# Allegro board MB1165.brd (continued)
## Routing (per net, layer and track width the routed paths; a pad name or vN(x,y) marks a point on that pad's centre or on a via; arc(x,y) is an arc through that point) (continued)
LCD_R4: length 172.7
  TOP w0.102: U4.N8 v5(74.81,136.89)
  TOP w0.127: v1(69.34,49.15) 69.34,51.31 70.99,52.96 81.41,52.96 87.31,47.05 CN18.11 ; v1(44.7,136.02) 43.43,136.02 42.55,136.91 CN5.31
  L3_SIG w0.102: v5(74.81,136.89) 74.19,136.27 73.66,136.27 73.18,135.79 71.27,135.79 70.65,135.17 68.16,135.17 66.85,133.86 56.31,133.86 54.03,136.14 44.83,136.14 v1(44.7,136.02)
  BOTTOM w0.127: v1(69.34,49.15) 64.52,49.15 61.59,52.07 61.59,61.94 53.16,70.37 53.16,80.67 44.55,89.28 44.55,106.45 39.52,111.48 39.52,123.77 36.96,126.34 36.96,131.44 38.61,133.1 43.29,133.1 43.54,133.35 44.7,133.35 45.34,133.99 45.34,135.38 v1(44.7,136.02)
LCD_R5: length 160.1
  TOP w0.127: U4.M9 v5(74.81,136.09) ; CN18.13 86.04,46.8 80.9,51.94 71.25,51.94 70.48,51.18 v1(70.48,50.55) ; CN5.34 v1(49.02,135.64)
  L3_SIG w0.102: v1(49.02,135.64) 53.9,135.64 56.06,133.48 67.03,133.48 68.31,134.76 70.82,134.76 71.32,135.25 73.41,135.25 74.04,135.89 74.55,135.89 74.75,136.09 v5(74.81,136.09)
  BOTTOM w0.127: v1(49.02,135.64) 45.34,131.95 43.94,131.95 43.56,131.57 39.88,131.57 39.62,131.32 38.86,131.32 38.48,130.94 38.48,127 41.05,124.43 41.05,112.33 46.3,107.07 46.3,90.42 54.58,82.14 54.58,71.34 63.65,62.27 63.65,53.06 66.04,50.67 70.36,50.67 v1(70.48,50.55)
LCD_R6: length 158.6
  TOP w0.127: CN5.42 45.21,130.56 45.09,130.43 v1(44.96,130.43) ; v5(74.41,130.36) 74.41,130.8 74.8,131.19 74.8,132.08 U4.M14 ; CN18.15 84.77,46.8 80.01,51.56 72.14,51.56 71.37,50.8 v1(71.37,50.55)
  L3_SIG w0.102: v1(44.96,130.43) 45.16,130.23 48.41,130.23 49.17,129.46 62.83,129.46 65.55,126.75 71.37,126.75 74.41,129.78 v5(74.41,130.36)
  BOTTOM w0.127: v1(71.37,50.55) 71.37,50.8 70.99,51.18 66.17,51.18 64.16,53.19 64.16,62.58 55.19,71.54 55.19,82.35 46.86,90.68 46.86,107.21 41.43,112.65 41.43,124.69 38.86,127.25 38.86,130.81 39.12,131.06 39.75,131.06 39.88,131.19 43.18,131.19 43.94,130.43 v1(44.96,130.43)
LCD_R7: length 148.7
  TOP w0.127: U4.J15 77.61,129.54 v3(75.94,127.87) ; v1(72.9,50.7) 73.25,51.05 79.63,51.05 83.5,47.18 CN18.17 ; CN5.51 v1(43.33,124.21)
  L3_SIG w0.102: v1(43.33,124.21) 43.94,124.21 44.7,124.97 47.5,124.97 47.88,125.35 49.53,125.35 50.42,124.46 62.48,124.46 64.01,122.94 73.91,122.94 74.68,123.7 74.68,126.61 v3(75.94,127.87)
  BOTTOM w0.127: v1(72.9,50.7) 72.9,51.18 71.95,52.13 67.25,52.13 65.25,54.13 65.25,63.11 56.21,72.15 56.21,83.49 47.75,91.95 47.75,107.95 42.19,113.51 42.19,123.06 v1(43.33,124.21)
LED_STLINK: length 38.9
  TOP w0.127: v1(16.26,16.51) R189.1 R188.1 ; v1(38.48,36.45) 38.22,36.71 U21.30
  BOTTOM w0.127: v1(16.26,16.51) 22.23,16.51 26.49,20.78 26.49,24 30.43,27.94 32.64,27.94 34.67,29.97 34.67,33.91 37.21,36.45 v1(38.48,36.45)
LOOP: length 5.6
  TOP w0.127: U22.14 61.81,31.41 64.01,29.21 TP15.1
MFX_SWCLK: length 7.6
  TOP w0.127: U22.37 51.26,36.41 50.16,35.31 46.61,35.31 CN21.3
MFX_SWDIO: length 11.6
  TOP w0.127: U22.34 54.51,39.6 53.72,40.39 46.61,40.39 CN21.1
MIC_CLK: length 137.6
  TOP w0.127: v1(119.13,16.38) 117.98,15.24 117.98,13.97 120.03,11.92 CN25.3
  BOTTOM w0.127: CN28.3 9.29,11.3 25.65,11.3 33.66,3.3 46.1,3.3 51.56,8.76 58.8,8.76 68.9,18.86 72.58,18.86 80.39,26.67 85.85,26.67 88.39,24.13 96.27,24.13 97.54,25.4 JP18.2 100.33,25.4 107.19,18.54 116.97,18.54 v1(119.13,16.38) SB25.1
MIC_DATA: length 154.5
  BOTTOM w0.127: CN25.1 128.38,11.92 130.68,14.22 130.68,15.88 130.05,16.51 SB26.2 128.78,17.14 121.54,17.14 118.62,20.07 107.57,20.07 100.97,26.67 97.03,26.67 95.76,25.4 JP17.2 89.66,25.4 85.98,29.08 81.41,29.08 72.52,20.19 67.56,20.19 56.77,9.4 51.31,9.4 45.59,3.68 34.29,3.68 26.16,11.81 11.18,11.81 9.78,13.21 5.32,13.21 CN28.1
MIC_VDD: length 156.3
  TOP w0.127: U25.1 125.65,15.66 126.36,16.38 C93.1 127.64,18.43 CN25.4 126.03,17.59 123,17.59 R186.2 120.4,14.99 R185.2 119.13,14.86 v1(118.87,15.11) ; v1(9.78,9.4) 9.4,9.02 8,9.02 7.49,9.53 6.48,9.53 5.63,8.68 U26.1
  L3_SIG w0.102: v1(9.78,9.4) 5.97,9.4 3.81,7.24 CN28.4
  BOTTOM w0.127: v1(9.78,9.4) 9.91,9.53 14.1,9.53 15.29,10.72 25.48,10.72 33.43,2.77 46.89,2.77 51.97,7.85 60.68,7.85 70.48,17.65 73.28,17.65 81.03,25.4 JP16.2 84.84,25.4 89.41,20.83 102.36,20.83 106.17,17.02 116.08,17.02 117.98,15.11 v1(118.87,15.11)
MII_TXD0: length 85.7
  TOP w0.127: v1(122.35,123.37) 122.53,123.54 U6.3 ; R36.2 91.69,142.24 92.75,141.19 101.56,141.19 v1(102.11,141.73)
  L3_SIG w0.102: v1(97.92,155.57) 98.81,156.46 102.36,156.46 103,157.1 107.7,157.1 v1(108.46,157.86)
  BOTTOM w0.127: v1(102.11,141.73) 102.11,146.05 98.17,149.99 98.17,155.32 v1(97.92,155.57) 97.33,156.16 SB27.1 ; v1(122.35,123.37) 122.35,127.25 121.51,128.09 121.51,137.44 116.31,142.65 111.56,142.65 111,143.21 111,155.32 v1(108.46,157.86)
NETB2_2: length 17.1
  TOP w0.127: B2.2 58.49,9.59 58.49,10.99 R205.1 R206.1 61.21,12.32 68.58,12.32 68.96,11.94 C103.2 68.96,9.53 B2.3
NETB3_2: length 17.7
  TOP w0.127: R204.1 R203.1 C100.2 89.73,13.15 B3.2 B3.3
NETB4_1: length 47.8
  TOP w0.127: U22.20 59.19,34.41 v1(58.88,34.09) ; B4.1 73.66,8.11 73.66,10.54 76.33,13.21 v1(77.98,13.21) 78.61,13.84 R199.2 C97.2
  L3_SIG w0.102: v1(77.98,13.21) 76.71,14.48 69.6,14.48 60.58,23.5 60.58,33.15 59.64,34.09 v1(58.88,34.09)
NETB4_2: length 43
  TOP w0.127: U22.18 v1(59.51,33.41) ; R198.2 C96.2 v1(74.42,13.08) 74.42,12.7 73.03,11.3 73.03,7.24 74.94,5.32 B4.2
  L3_SIG w0.102: v1(59.51,33.41) 59.69,33.41 60.33,32.77 60.33,23.11 69.47,13.97 73.53,13.97 v1(74.42,13.08)
NETB4_3: length 45.3
  TOP w0.127: v1(58.88,33.4) 59.38,33.9 U22.19 ; C95.2 R197.2 v1(73.03,13.08) 72.52,12.57 72.52,6.6 74.8,4.32 77.45,4.32 B4.3
  L3_SIG w0.102: v1(58.88,33.4) 59.97,32.31 59.97,22.83 69.72,13.08 v1(73.03,13.08)
NETB4_4: length 55.4
  TOP w0.127: U22.39 52.68,35.41 53.09,35.81 53.7,35.81 v1(53.82,35.69) ; B4.4 84.84,11.31 v1(84.84,13.08) 84.84,13.34 R201.2 C99.2
  L3_SIG w0.102: v1(84.84,13.08) 82.3,15.62 69.6,15.62 61.34,23.88 61.34,33.53 60.1,34.77 54.74,34.77 v1(53.82,35.69)
NETB4_6: length 49.3
  TOP w0.127: v1(53.09,35.18) 52.96,35.18 52.68,34.9 U22.40 ; C98.2 R200.2 81.79,13.59 v1(81.79,13.07) B4.6
  L3_SIG w0.102: v1(81.79,13.07) 79.87,14.99 69.66,14.99 68.73,15.91 64.93,19.71 60.96,23.68 60.96,33.4 59.82,34.54 53.72,34.54 v1(53.09,35.18)
NETBT1_1: length 23.8
  TOP w0.254: BT1.1 47.88,78.23 40.77,85.34 JP10.3
NETC2_1: length 6.9
  TOP w0.508: C4.1 137.79,167.26 C2.1 R1.2 134.85,168.68 U1.6
NETC5_1: length 10
  TOP w0.508: R16.2 138.3,158.2 ; R16.2 137.69,157.61 ; R16.2 138.91,157.61 ; U2.1 135.85,159.11 ; U2.1 135.14,160.21 ; U2.1 135.14,158 ; U2.1 134.43,159.11 ; 137.69,159.13 R7.1 ; R7.1 138.3,158.53 ; R7.1 138.91,159.13 ; C5.1 135.84,161.93 ; C5.1 135,162.89 ; C5.1 135,160.96
NETC6_2: length 50.9
  TOP w0.127: CN1.31 64.01,166.53 v1(64.01,163.96) 64.01,160.2 64.17,160.04 65.55,160.04 C6.2
  BOTTOM w0.127: v1(64.01,163.96) 57.15,163.96 51.82,158.62 42.29,158.62 38.61,154.94 38.61,145.29 39.5,144.4 SB46.1
NETC7_2: length 81.8
  TOP w0.127: CN1.27 71.63,166.21 71.63,162.31 72.14,161.8 C7.2
  TOP w0.155: v1(69.44,157.84) 69.6,157.99 69.6,159.89 69.98,160.27 C7.2
  BOTTOM w0.127: 116.2,133.1 SB66.1 115.32,133.99 108.2,133.99 106.3,135.89 106.3,153.06 102.86,156.5 102.86,157.75 101.55,159.05 93.65,159.05 93.24,158.65 80.82,158.65 80.34,158.17 70,158.17 69.67,157.84 v1(69.44,157.84)
NETC8_2: length 27
  TOP w0.127: CN1.33 61.09,166.15 v1(61.09,162.62) C8.2
  BOTTOM w0.127: SB33.1 48.9,152.02 48.9,153.16 58.36,162.62 v1(61.09,162.62)
NETC9_2: length 34.5
  TOP w0.127: C9.2 v1(62.48,161.99) 62.48,165 CN1.34
  BOTTOM w0.127: v1(62.48,161.99) 62.29,161.8 59.56,161.8 50.67,152.91 50.67,151.83 49.94,151.09 49.94,150.01 48.39,148.46 45.47,148.46 44.7,147.7 43.69,147.7 42.71,146.72 41.24,146.72 40.64,147.32
NETC10_2: length 76.9
  TOP w0.127: v1(68.55,156.16) 68.07,156.64 68.07,159.51 C10.2 68.83,166.47 CN1.29
  BOTTOM w0.127: SB68.1 108.58,131.44 108.58,133.15 105.92,135.81 105.92,153.03 101.73,157.23 101.73,157.66 100.91,158.47 95.1,158.47 94.39,157.76 81.25,157.76 80.87,157.38 70.51,157.38 69.8,156.67 69.06,156.67 v1(68.55,156.16)
NETC11_1: length 47.2
  TOP w0.127: v1(74.5,158.65) 74.6,158.75 R8.2 C11.1
  BOTTOM w0.127: SB69.2 50.32,133.25 50.32,138.48 55.02,143.18 55.02,148.91 60.35,154.24 63.39,154.24 67.44,158.29 69.19,158.29 69.32,158.42 74.27,158.42 v1(74.5,158.65)
NETC12_2: length 48.1
  TOP w0.127: C12.2 R9.1 78.51,159.74 v1(78.51,160.27)
  BOTTOM w0.127: v1(78.51,160.27) 77.6,160.27 76.96,159.64 73.43,159.64 73.18,159.38 69.04,159.38 68.78,159.13 66.67,159.13 63.5,155.96 60.33,155.96 53.75,149.38 53.75,143.66 48.51,138.43 48.51,137.41 47.75,136.65
NETC13_2: length 54.7
  TOP w0.127: C13.2 R10.1 81.97,159.59 v1(81.97,160.73)
  BOTTOM w0.127: SB49.2 44.83,141.35 45.59,142.11 49.15,142.11 52.6,145.57 52.6,150.01 59.69,157.1 62.99,157.1 66.07,160.17 67.87,160.17 68.39,160.7 72.97,160.7 73.17,160.5 76.28,160.5 76.97,161.19 81.51,161.19 v1(81.97,160.73)
NETC14_2: length 52
  TOP w0.127: v1(85.9,162.92) 85.85,162.86 85.85,162.31 86.23,161.93 86.23,159.38 R11.1 C14.2
  BOTTOM w0.127: SB41.2 48.39,147.57 50.39,149.58 50.39,150.85 51.44,151.89 51.44,152.78 59.94,161.29 63.63,161.29 65.38,163.04 85.78,163.04 v1(85.9,162.92)
NETC15_1: length 92.3
  TOP w0.127: C15.1 R13.1 R12.2 89.15,159.51 89.15,165.99 88.77,166.37 87.38,166.37 86.49,167.26 86.49,168.5 v1(86.36,168.63)
  BOTTOM w0.127: v1(86.36,168.63) 86.11,168.88 44.68,168.88 42.55,166.75 42.55,160.66 37.21,155.32 37.21,143.89 38.02,143.08 38.02,140.59 38.53,140.08 40.39,140.08 40.64,139.83 SB52.2
NETC16_2: length 10.6
  TOP w0.127: R15.1 R14.1 C16.2 104.27,166.59 CN1.1
NETC17_1: length 1.7
  TOP w0.127: 64.14,159.05 64.32,158.88 C17.1
NETC18_2: length 78.4
  TOP w0.127: SB1.1 70.49,159 70.49,157.36 v1(69.34,156.21) ; C18.2 70.87,158.88
  BOTTOM w0.127: v1(69.34,156.21) 69.77,156.21 70.66,157.1 81.13,157.1 81.51,157.48 94.61,157.48 95.18,158.05 99.2,158.05 100.41,156.84 100.89,156.84 105.21,152.53 105.21,135.61 107.59,133.22 107.59,127.64 107.87,127.36 112.27,127.36 112.67,127.76 115.32,127.76 SB75.1
NETC20_1: length 6.3
  TOP w0.203: X1.2 75.44,152.65 C20.1 R20.2
NETC21_1: length 5.7
  TOP w0.203: X2.1 82.63,153.46 82.63,152.6 82.09,152.06 82.09,151.17 C21.1 R18.1
NETC22_1: length 5.7
  TOP w0.203: X2.2 83.06,153.28 83.06,152.4 82.51,151.85 82.51,151.02 C22.1 R19.1
NETC24_2: length 2.8
  TOP w0.127: R30.1 C24.2 R31.1
NETC25_1: length 2.4
  TOP w0.127: C25.1 26.89,133.77 U5.1
NETC25_2: length 2.1
  TOP w0.127: C25.2 26.02,133.12 U5.2
NETC27_2: length 2.4
  TOP w0.127: C27.2 26.67,132.47 U5.3
NETC30_1: length 13.9
  TOP w0.254: JP7.1 145.29,125.22 X4.1 137.54,125.22 C30.1
NETC32_1: length 12.3
  TOP w0.127: v5(81.21,134.49) U4.E11
  TOP w0.508: C32.1 82.09,125.81 80.53,127.36 80.53,128.21 80.49,128.25 80.49,129.46 80.06,129.9 v1(79.86,129.9)
  BOTTOM w0.127: v5(81.21,134.49) 80.83,134.11 80.16,134.11 80.04,133.99 80.04,132.37 80.01,132.33
  BOTTOM w0.381: v1(79.86,129.9) 79.93,129.97 79.93,130.56 80.01,130.63 80.01,132.33
NETC33_2: length 7.2
  TOP w0.254: X4.2 140.72,121.23 139.14,122.81 R67.2 C33.2
NETC35_1: length 21.4
  TOP w0.508: L1.2 7.21,118.11 ; L1.2 6.6,118.76 ; L1.2 6.6,117.46 ; L1.2 5.99,118.11 ; 1.28,118.21 CN8.8 2.44,117.31 ; C36.1 5.69,118.11 ; C36.1 4.47,118.11 ; C36.1 5.08,117.46 ; 2.44,109.01 CN8.9 1.28,108.1 ; 4.47,107.95 C45.1 ; C45.1 5.08,108.6 ; C45.1 5.69,107.95 ; 3.56,117.46 C35.1 ; C35.1 4.17,118.11 ; C35.1 2.95,118.11 ; C44.1 4.17,107.95 ; C44.1 2.95,107.95 ; C44.1 3.56,108.6 ; CN8.6 5.46,110.88 ; CN8.6 3.46,110.88 ; CN8.6 4.46,110.14 ; CN8.7 5.46,115.43 ; CN8.7 4.46,116.17 ; CN8.7 3.46,115.43 ; 5.01,114.46 CN8.5 3.26,114.46
NETC37_1: length 8.8
  TOP w0.508: SB13.1 11.43,115.82 12.07,116.46 13.84,116.46 SB14.2 15.62,116.46 C37.1 17.09,116.26 U7.1
NETC39_1: length 8
  TOP w0.203: U8.28 28.7,109.86 R81.2 C39.1 27.81,113.54 X5.1
NETC40_1: length 7.6
  TOP w0.203: U8.27 29.2,110.61 R81.1 C40.1 29.34,113.54 X5.2
NETC41_1: length 12.4
  TOP w0.102: U9.B5 81.31,102.77 83.11,102.77 83.79,103.45 83.79,105.87 84,106.07 84,107.95
  TOP w0.127: 84,107.95 84,110.41 C41.1 R79.2
NETC42_1: length 5
  TOP w0.127: U8.29 28.2,109.72 27.81,110.11 v1(27.05,110.11) 26.92,110.11 C42.1
  BOTTOM w0.127: C147.1 26.67,110.11 v1(27.05,110.11)
NETC43_1: length 19.7
  TOP w0.254: U8.15 29.7,102.74 ; v1(30.1,111.53) 30.23,111.53 30.86,110.9 C43.1 29.7,109.58 U8.26
  TOP w0.381: v1(32,102.79) 32,101.47 C48.1 31.11,101.35 29.97,102.49 29.95,102.49 29.7,102.74
  BOTTOM w0.381: v1(32,102.79) 32,103 32.64,103.63 32.64,105.28 32.72,105.36 32.72,109.7 30.89,111.53 v1(30.1,111.53)
NETC53_2: length 1.9
  TOP w0.508: C53.2 24.2,69.78 U17.4
NETC54_2: length 21.8
  TOP w0.508: C54.2 30.17,69.78 U17.3 ; C54.2 30.23,73.12 29.06,74.28 D12.2 D11.2 D10.2 D9.2 D8.2 D7.2 ; C54.2 C56.2 28.32,67.82 U17.1
NETC63_1: length 9
  TOP w0.508: 65.53,51.47 L4.2 66.14,52.12 ; 65.91,48.31 65.91,49.28 ; 65.91,48.31 65.07,48.31 ; 65.91,48.31 65.91,47.35 ; 65.91,48.31 66.75,48.31 ; 65.28,49.73 C63.1 ; C63.1 65.93,50.34 ; C63.1 65.28,50.95 ; CN18.45 65.72,46.75
NETC63_2: length 11.3
  TOP w0.508: 63.18,46.1 CN18.49 62.61,44.5 ; 62.28,48.31 C66.2 ; C66.2 63.96,48.31 ; C66.2 63.12,47.35 ; C66.2 63.12,49.28 ; L3.2 64.11,52.12 ; L3.2 62.89,52.12 ; L3.2 63.5,51.47 ; 63.75,49.73 C63.2 ; C63.2 63.75,50.95 ; C63.2 63.11,50.34 ; CN18.47 64.45,46.27
NETC64_1: length 27.8
  TOP w0.508: 22.1,46.83 D13.3 ; D13.3 22.1,47.85 ; D13.3 22.77,47.34 ; Z1.2 23.24,52.35 ; Z1.2 22.03,51.31 ; Z1.2 24.44,51.31 ; Z1.2 23.24,50.27 ; C64.1 22.1,49.38 ; C64.1 22.1,48.16 ; C64.1 22.75,48.77
  TOP w1.143: 22.15,53.19 21.62,53.72 12.7,53.72 11.68,52.7 9.02,52.7 6.52,50.2 L5.1
NETC64_2: length 27
  TOP w0.508: 19.44,50.27 Z1.1 ; Z1.1 20.64,51.31 ; Z1.1 19.44,52.35 ; Z1.1 18.23,51.31 ; 19.93,48.77 C64.2 ; C64.2 20.57,49.38 ; C64.2 20.57,48.16 ; 20.15,47.34 D13.2 ; D13.2 20.83,47.85 ; D13.2 20.83,46.83 ; 7.91,50.2 L5.2 ; L5.2 10.3,50.2 ; L5.2 9.1,51.4 ; L5.2 9.1,49.01 ; CN19.2 7.54,35.84 ; CN19.2 9.86,34.62 ; CN19.2 5.23,34.62 ; CN19.2 7.54,33.4 ; 4.45,37.31 CN19.3 ; CN19.3 3.23,39.62 ; CN19.3 5.66,39.62 ; CN19.3 4.45,41.94
NETC68_2: length 5.9
  TOP w0.127: C68.2 113.92,33.25 114.53,32.64 116.46,32.64 117.36,31.74 U23.C9
NETC69_1: length 5.6
  TOP w0.127: v1(115.01,33.53) 115.01,34.11 C69.1 ; U23.D7 v2(117.61,30.33)
  L3_SIG w0.102: v2(117.61,30.33) 115.01,32.93 v1(115.01,33.53)
NETC69_2: length 60.7
  TOP w0.127: R212.2 140.37,1.18 CN27.2 136.51,1.18 v1(135.2,2.49) ; v1(114.58,35.18) 114.68,35.28 114.68,35.31 C69.2 ; R160.1 v1(111.63,27.58)
  L3_SIG w0.102: v1(135.2,2.49) 132.51,2.49 130.81,4.19 130.81,6.99 127.64,10.16 119.89,10.16 111.63,18.41 v1(111.63,27.58)
  BOTTOM w0.127: v1(114.58,35.18) 113.41,34.01 113.41,31.95 111.63,30.17 v1(111.63,27.58)
NETC70_1: length 3.8
  TOP w0.127: U23.D9 117.86,32.38 116.71,33.53 C70.1
NETC74_1: length 7.2
  TOP w0.127: U23.E6 v2(118.61,29.83) ; C74.1 v1(122.3,33.53)
  L3_SIG w0.102: v2(118.61,29.83) 119.02,30.25 119.02,30.76 119.38,31.11 120.65,31.11 121.89,32.36 121.89,33.12 v1(122.3,33.53)
NETC75_1: length 6.2
  TOP w0.127: U23.H8 120.85,30.58 122.45,32.18 124.38,32.18 C75.1
NETC75_2: length 5.4
  TOP w0.127: U23.G8 v2(119.61,30.83) ; v1(122.53,32.74) 123.42,32.74 C75.2
  L3_SIG w0.102: v1(122.53,32.74) 122.53,32.36 121,30.83 v2(119.61,30.83)
NETC76_2: length 37.9
  TOP w0.127: U23.A7 115.13,30.08 v1(114.02,31.19) 113.21,32 C76.2
  L3_SIG w0.102: v1(114.02,31.19) 113.72,31.5 96.01,31.5 90.93,26.42 87.38,26.42 JP16.1
NETC77_1: length 4.8
  TOP w0.127: v2(119.61,30.33) 119.36,30.08 U23.G7 ; C77.1 v1(122.63,31.5)
  L3_SIG w0.127: v1(122.63,31.5) 121.47,30.33 v2(119.61,30.33)
NETC78_2: length 5.7
  TOP w0.127: C78.2 R160.2 v1(114.07,29.21) ; v2(116.61,29.33) 116.86,29.58 U23.B6
  L3_SIG w0.102: v1(114.07,29.21) 114.73,29.87 116.1,29.87 116.61,29.36 v2(116.61,29.33)
NETC79_1: length 3.8
  TOP w0.127: U23.H7 123.43,30.08 C79.1
NETC80_1: length 34.6
  TOP w0.127: C80.1 122.94,28.83 v1(122.73,29.03) ; v1(132.31,6.2) 131.99,5.88 CN27.4 ; U23.G6 v2(119.61,29.83)
  L3_SIG w0.102: v1(132.31,6.2) 132.31,16.79 127.95,21.15 127.95,25.59 125.86,27.69 124.08,27.69 v1(122.73,29.03) 121.93,29.83 v2(119.61,29.83)
NETC80_2: length 1.7
  TOP w0.127: C80.2 R161.1
NETC81_1: length 28.6
  TOP w0.127: v1(124.33,28.19) C81.1 122.1,27.43 119.95,29.58 U23.H6 ; CN27.6 137.32,14.33 v1(135.74,14.33)
  L3_SIG w0.102: v1(124.33,28.19) 125.98,28.19 128.22,25.96 128.22,21.39 135.28,14.33 v1(135.74,14.33)
NETC81_2: length 1.7
  TOP w0.127: C81.2 R162.1
NETC82_2: length 8
  TOP w0.279: U22.9 57.51,27.07 C82.2
  TOP w0.508: C82.2 57.53,26.04 57.78,25.78 57.78,24.26 56.39,22.86 55.88,22.86 L6.2
NETC83_2: length 5.2
  TOP w0.127: U22.7 56.51,27.81 C83.2 R165.1 53.45,27.05 D16.1
NETC91_1: length 4.1
  TOP w0.127: U23.F1 118.67,26.89 118.67,26.37 C91.1
NETC92_1: length 2.5
  TOP w0.127: R183.1 R184.1 C92.1
NETC92_2: length 12.8
  TOP w0.254: U23.A2 116.23,27.58 115.95,27.3 115.65,27.3 115.62,27.33
  TOP w0.508: C92.2 114.17,18.67 112.78,20.07 112.78,24.89 115.21,27.33 115.62,27.33
NETC100_1: length 1.4
  TOP w0.127: C100.1 R202.2
NETC101_1: length 3.1
  TOP w0.127: R209.2 R208.2 106.55,11.3 C101.1
NETC101_2: length 21.7
  TOP w0.229: U23.B3 v2(116.61,28.33)
  TOP w0.508: C101.2 106.68,20.95 v1(113.92,28.19)
  L3_SIG w0.381: v1(113.92,28.19) 114.45,28.73 116.22,28.73 v2(116.61,28.33)
NETC103_1: length 1.5
  TOP w0.127: C103.1 R207.2
NETC137_2: length 2.7
  TOP w0.127: v1(33.4,133.22) 33.51,133.12 U5.27
  BOTTOM w0.127: v1(33.4,133.22) 34.04,132.59 C137.2
NETC139_1: length 4.9
  TOP w0.127: U5.24 34.19,131.17 34.04,131.32 32,131.32 v1(31.5,131.83)
  BOTTOM w0.127: v1(31.5,131.83) C139.1
NETC139_2: length 4.8
  TOP w0.127: U5.28 31.91,133.77 v1(31.5,133.35)
  BOTTOM w0.127: v1(31.5,133.35) C139.2
NETC142_2: length 9.2
  TOP w0.254: U6.37 130.77,125.31 v1(130.3,124.84) ; U6.18 v1(127.77,116.33) ; U6.23 130.27,116.37 v1(130.3,116.33)
  BOTTOM w0.508: C144.1 130.3,124.08 v1(130.3,124.84) C142.2 ; v1(127.77,116.33) 127.38,116.72 C146.2 ; C145.1 v1(130.3,116.33)
NETC143_1: length 10.2
  TOP w0.127: U4.L11 v5(75.61,134.49)
  BOTTOM w0.127: v5(75.61,134.49) 75.61,134.22 76.01,133.82 76.01,132.65 76.15,132.51 76.48,132.51 76.83,132.16
  BOTTOM w0.381: 76.83,132.16 76.83,129.29 76.96,129.16 76.96,127.59 77.47,127.08 77.47,126.57 C143.1
NETC155_1: length 8.3
  TOP w0.254: CN15.23 105.32,86.19 v1(105.57,85.93) 105.82,86.18 CN15.21
  BOTTOM w0.508: C155.1 106.33,87.11 105.57,86.35 v1(105.57,85.93) 105.57,84.69 C156.1 L8.2
NETC155_2: length 8.1
  TOP w0.254: CN15.27 104.32,86.03 v1(104.17,85.88) 103.82,86.22 CN15.29
  BOTTOM w0.508: C155.2 104.17,86.61 v1(104.17,85.88) 104.17,84.58 C156.2 L9.2
NETCN1_3: length 74.4
  L3_SIG w0.102: v1(130.18,136.4) 129.67,135.89 129.67,133.86 123.95,128.14 121.67,128.14 117.27,123.75 v1(117.27,121.21)
  BOTTOM w0.127: v1(117.27,121.21) 116.08,122.4 SB82.2 ; CN1.3 101.9,168.86 110.03,168.86 125.98,152.91 125.98,151.71 130.35,147.35 130.35,136.58 v1(130.18,136.4)
NETCN1_5: length 64
  TOP w0.127: CN1.5 96.9,166.4 v1(96.9,162.13)
  BOTTOM w0.127: v1(96.9,162.13) 86.82,162.13 86.49,161.8 85.01,161.8 84.68,162.13 66.24,162.13 63.37,159.26 59.82,159.26 51.23,150.67 51.23,147.62 49.66,146.05 SB43.1
NETCN1_9: length 81.4
  TOP w0.127: CN1.9 94.11,166.59 v1(94.11,158.22)
  L3_SIG w0.102: v1(49.63,131.01) 48.69,131.95 45.9,131.95 45.36,132.49 43.87,132.49 43.18,133.17 v1(43.18,133.66)
  BOTTOM w0.127: v1(43.18,133.66) 43.17,133.66 42.98,133.86 SB64.1 ; v1(49.63,131.01) 51.08,132.46 51.08,138.25 55.75,142.93 55.75,148.56 60.63,153.45 65.05,153.45 68.55,156.95 69.62,156.95 70.33,157.66 80.7,157.66 81.08,158.04 93.93,158.04 v1(94.11,158.22)
NETCN1_11: length 56.2
  TOP w0.127: v1(92.84,156.95) 92.84,161.16 91.69,162.31 91.69,166.47 CN1.11
  BOTTOM w0.127: SB78.2 110.74,125.98 110.49,126.24 106.76,126.24 106.45,126.54 106.45,132.28 103.73,135 103.73,151.92 100.57,155.08 100.34,155.08 98.83,156.59 97.13,156.59 96.67,157.05 92.94,157.05 v1(92.84,156.95)
NETCN1_13: length 88.7
  TOP w0.127: v1(87.5,169.42) 87.98,168.94 CN1.13
  BOTTOM w0.127: SB61.1 41.78,135.76 41.02,136.53 36.45,136.53 35.48,137.49 35.48,143.05 36.45,144.02 36.45,158.62 41.53,163.7 41.53,167.51 43.69,169.67 87.25,169.67 v1(87.5,169.42)
NETCN1_14: length 5
  TOP w0.127: CN1.14 88.39,164.69 R12.1
NETCN1_15: length 8.5
  TOP w0.127: CN1.15 84.2,166.4 84.2,163.58 85.09,162.69 85.09,160.78 R11.2
NETCN1_17: length 8.1
  TOP w0.127: CN1.17 81.92,166.65 81.92,163.83 82.8,162.94 R10.2
NETCN1_19: length 7.9
  TOP w0.127: CN1.19 79.3,166.58 79.3,160.48 R9.2
NETCN1_21: length 62.2
  TOP w0.127: CN1.21 78.84,166.62 78.84,161.26 78.03,160.45 78.03,159.65 78.37,159.31 v1(78.37,159.25)
  BOTTOM w0.127: SB60.2 108.08,136.91 108.08,154.43 106.3,156.21 106.3,157.86 104.18,159.98 93.21,159.98 92.68,159.46 81.2,159.46 80.59,160.07 79.55,160.07 78.73,159.25 v1(78.37,159.25)
NETCN1_23: length 62
  TOP w0.127: CN1.23 76.61,166.32 76.61,163.27 77.6,162.28 v1(77.6,159.26)
  BOTTOM w0.127: 108.99,137.44 108.46,137.97 108.46,154.81 106.81,156.46 106.81,158.09 104.58,160.31 93.05,160.31 92.46,159.72 81.38,159.72 80.75,160.35 79.32,160.35 78.73,159.77 78.11,159.77 v1(77.6,159.26)
NETCN1_26: length 5.9
  TOP w0.127: CN1.26 75.31,162.53 R8.1
NETCN2_1: length 3.1
  TOP w0.127: R4.2 CN2.1
NETCN2_3: length 3.1
  TOP w0.127: R5.2 36.16,163.96 CN2.3
NETCN2_4: length 9
  TOP w0.127: CN2.4 25.91,163.83 24.77,162.69 24.77,157.1 R17.1
NETCN3_1: length 4.8
  TOP w0.127: R29.1 R30.2 CN3.1
NETCN4_15: length 178.8
  TOP w0.127: v1(54.99,36.83) 55.01,36.85 U22.33 ; v1(150.75,149.48) 150.53,149.69 CN4.15
  L3_SIG w0.102: v1(54.99,36.83) 56.26,38.1 63.25,38.1 64.9,39.75 78.99,39.75 109.73,70.48 111.25,70.48 111.95,71.18 111.95,74.38 117.09,79.53 117.09,89.15 125.73,97.79 126.62,97.79 130.4,101.57 130.4,105.77 134.24,109.6 136.63,109.6 141.02,114 142.82,114 146.43,117.6 150.55,117.6 155.19,122.25 155.19,134.11 153.42,135.89 153.42,146.61 151.26,148.77 151.26,148.97 v1(150.75,149.48)
  BOTTOM w0.127: v1(150.75,149.48) R218.2
NETCN4_17: length 175.9
  TOP w0.127: U22.32 55.51,39.1 v1(55.37,39.24) ; CN4.17 149.81,148.69 149.81,148.69 v1(150.75,148.69)
  L3_SIG w0.102: v1(150.75,148.69) 150.77,148.69 153.09,146.38 153.09,135.25 154.43,133.91 154.43,122.3 150.5,118.36 146.3,118.36 142.68,114.74 141.03,114.74 136.53,110.24 133.48,110.24 129.79,106.55 129.79,101.5 126.67,98.37 125.53,98.37 115.57,88.42 115.57,81.03 114.81,80.26 114.81,77.98 111.25,74.42 111.25,72.52 78.87,40.13 63.37,40.13 61.59,38.35 56.26,38.35 v1(55.37,39.24)
  BOTTOM w0.127: v1(150.75,148.69) 150.27,148.69 R220.1
NETCN4_18: length 6.1
  TOP w0.127: TP7.1 154.94,147.8 154.05,148.69 CN4.18
NETCN4_19: length 174.4
  TOP w0.127: U22.31 56.01,39.12 v1(56.13,39.24) ; v1(151.13,147.22) 150.29,147.22 149.82,147.69 CN4.19
  L3_SIG w0.102: v1(56.13,39.24) 56.64,38.73 61.47,38.73 63.12,40.39 78.63,40.39 110.91,72.66 110.91,74.58 114.36,78.04 114.36,80.33 115.19,81.15 115.19,88.52 125.42,98.76 126.69,98.76 129.54,101.6 129.54,107.06 133.86,111.38 137.31,111.38 140.98,115.05 142.61,115.05 146.18,118.62 150.39,118.62 154.05,122.28 154.05,133.83 152.83,135.05 152.83,146 151.61,147.22 v1(151.13,147.22)
  BOTTOM w0.127: v1(151.13,147.22) 150.6,147.22 149.73,146.35 R225.1
NETCN4_31: length 134.6
  TOP w0.127: CN4.31 v1(150.5,141.69)
  L3_SIG w0.102: v1(122.81,147.57) 123.83,148.59 129.41,148.59 135.76,154.94 142.95,154.94 145.14,152.76 145.14,145.47 148.91,141.69 v1(150.5,141.69)
  BOTTOM w0.127: SB47.1 48.44,143 52.1,146.66 52.1,150.39 60.07,158.37 63.5,158.37 65.79,160.66 67.89,160.66 68.33,161.09 73.03,161.09 73.36,160.76 76.18,160.76 76.92,161.49 81.97,161.49 82.93,160.53 91.74,160.53 92.55,161.33 98.21,161.33 98.68,161.8 105.11,161.8 107.98,158.93 112.75,158.93 118.24,153.44 118.24,152.15 v1(122.81,147.57)
NETCN4_34: length 2.9
  TOP w0.127: TP8.1 154.03,140.69 CN4.34
NETCN4_35: length 11
  TOP w0.127: CN4.35 148.71,139.69 148.21,139.19 148.21,137.16 149.66,135.71 154.25,135.71 TP11.1
NETCN4_36: length 2.8
  TOP w0.127: TP10.1 154.31,139.69 CN4.36
NETCN5_3: length 40.6
  TOP w0.127: CN5.3 42.57,154.69 43.03,154.23 v1(43.31,154.23)
  L3_SIG w0.102: v1(43.31,154.23) 44.86,154.23 45.77,155.14 64.57,155.14 67.11,152.6 70.54,152.6 73.03,150.11 77.87,150.11 v1(78.11,149.88)
  BOTTOM w0.127: 76.93,149.88 v1(78.11,149.88)
NETCN5_5: length 3.9
  TOP w0.127: CN5.5 40.26,153.42 39.5,154.18 v1(39.5,154.69)
  BOTTOM w0.127: R213.2 39.88,155.07 v1(39.5,154.69)
NETCN5_6: length 29.3
  TOP w0.127: v1(49,154.56) 47.85,153.42 CN5.6
  L3_SIG w0.102: v1(72.39,150.11) 71.88,150.11 69.77,152.22 66.85,152.22 64.52,154.56 v1(49,154.56)
  BOTTOM w0.127: 73.76,149.88 72.62,149.88 v1(72.39,150.11)
NETCN6_3: length 37.4
  TOP w0.127: v1(111.81,154.05) 111.79,154.05 111.15,154.69 CN6.3
  L3_SIG w0.102: v1(79.22,150.22) 80.21,150.22 80.57,150.57 87.68,150.57 91.31,154.2 111.66,154.2 v1(111.81,154.05)
  BOTTOM w0.127: v1(79.22,150.22) 80.24,150.22 SB36.2
NETCN6_4: length 35
  TOP w0.127: v1(113.49,154.13) 113.61,154.13 114.17,154.69 CN6.4
  L3_SIG w0.102: v1(84.02,151.61) 84.71,150.93 87.5,150.93 91.16,154.58 111.94,154.58 112.39,154.13 v1(113.49,154.13)
  BOTTOM w0.127: v1(84.02,151.61) 83.95,151.54 SB35.2
NETCN7_2: length 27
  TOP w0.127: U5.6 28.92,130.52 29.84,131.44 29.84,134.62 25.65,138.81 10.77,138.81 CN7.2
NETCN7_3: length 21.2
  TOP w0.127: CN7.3 11.68,136.53 20.29,127.91 U5.10
NETCN7_6: length 28.9
  TOP w0.127: U5.5 28.68,131.17 29.21,131.7 29.21,134.49 25.65,138.05 9.53,138.05 7.49,140.08 CN7.6
NETCN7_8: length 26.1
  TOP w0.127: CN7.8 7.49,135.76 9.4,137.67 11.68,137.67 20.7,128.65 25.91,128.65 27.12,129.87 U5.7
NETCN8_2: length 27.8
  TOP w0.155: U8.8 25.65,104.29 25.59,104.35 25.39,104.35 25.26,104.23 23.48,104.23 v1(23.34,104.09) ; CN8.2 4.99,112.51 5.12,112.64 5.61,112.64 7.46,114.49 7.8,114.49 D4.A1 7.8,114.37 8.2,113.97 v1(8.44,113.97)
  L3_SIG w0.13: v1(23.34,104.09) 23.2,104.23 22.74,104.23 21.38,105.59 20.62,105.59 11.6,114.6 9.47,114.6 8.84,113.97 v1(8.44,113.97)
NETCN8_3: length 27.7
  TOP w0.155: v1(8.38,115.44) 8.2,115.44 7.8,115.04 D4.A2 7.79,114.87 7.3,114.87 5.45,113.02 5.12,113.02 4.99,113.16 CN8.3 ; U8.7 25.71,104.8 25.65,104.74 25.23,104.74 25.11,104.61 23.48,104.61 v1(23.34,104.75)
  L3_SIG w0.13: v1(23.34,104.75) 23.2,104.61 22.9,104.61 21.54,105.97 20.78,105.97 11.76,114.99 9.42,114.99 8.97,115.44 v1(8.38,115.44)
NETCN8_4: length 29
  TOP w0.127: CN8.4 5.35,113.81 6.48,114.94 6.48,115.95 7.06,116.53 D3.A2 7.8,116.81 8.08,117.09 v1(8.66,117.09) ; v1(23.37,105.8) U8.5
  L3_SIG w0.102: v1(8.66,117.09) 12.22,117.09 14.61,114.71 14.61,114.13 22.94,105.8 v1(23.37,105.8)
NETCN9_1: length 35.8
  TOP w0.13: U6.17 127.27,118.34 127.21,118.4 127.21,118.69 126.85,119.04 125.14,119.04 123.95,117.86 123.95,114.35 132.72,105.59 132.72,103.98 134.59,102.11 136.78,102.11 R110.2 138.05,102.11 142.39,102.11 143.06,102.79 143.3,102.79 CN9.1
NETCN9_2: length 35.7
  TOP w0.13: U6.16 126.77,118.34 126.83,118.4 126.83,118.53 126.7,118.66 125.29,118.66 124.33,117.7 124.33,117.44 124.54,117.24 124.54,116.98 124.33,116.78 124.33,116.52 124.54,116.31 124.54,116.05 124.33,115.85 124.33,115.59 124.54,115.39 124.54,115.13 124.33,114.93 124.33,114.51 133.1,105.75 133.1,104.14 134.75,102.49 136.78,102.49 R105.2 138.05,102.49 142.23,102.49 142.9,103.16 142.9,104.01 142.77,104.14 141.73,104.14 141.6,104.01 141.6,103.63
NETCN9_3: length 28
  TOP w0.13: U6.14 125.77,116.55 125.71,116.49 125.71,114.58 130.18,110.11 136.91,110.11 R83.2 138.18,110.11 142.62,110.11 143.13,109.6 143.13,105.92 CN9.3
NETCN9_6: length 28.1
  TOP w0.13: 141.6,108.71 141.48,108.71 141.35,108.58 141.35,107.42 141.48,107.29 142.62,107.29 142.75,107.42 142.75,109.44 142.46,109.73 138.18,109.73 R90.2 136.91,109.73 130.02,109.73 125.33,114.42 125.33,116.49 125.27,116.55 U6.13
NETCN9_9: length 3.7
  TOP w0.127: R118.1 155.39,97.74 CN9.9
NETCN9_10: length 40.6
  TOP w0.127: U6.28 132.95,120.54 134.49,119 134.87,119 R70.1 135.89,117.98 137.79,117.98 139.01,116.76 148.79,116.76 150.34,118.31 154.86,118.31 v1(155.07,118.11)
  BOTTOM w0.127: CN9.10 153.87,111.2 155.07,112.39 v1(155.07,118.11)
NETCN9_11: length 32.7
  TOP w0.127: U6.26 132.98,119.54 133.86,118.67 133.86,117.22 R73.1 135.86,116.43 148.97,116.43 150.39,117.86 154.05,117.86 155.39,116.51 CN9.11
NETCN9_12: length 3.7
  TOP w0.127: R72.1 153.87,116 CN9.12
NETCN11_6: length 49.3
  TOP w0.102: 82.98,107.95 82.98,104.44 U9.A4
  TOP w0.127: R86.1 82.75,110.57 82.75,108.99 v4(83.13,108.61) 82.98,108.46 82.98,107.95 ; v3(103.5,114.68) 103.68,114.86 CN11.6
  L3_SIG w0.102: v3(103.5,114.68) 103,114.17 101.88,114.17 96.89,109.18 84.42,109.18 83.85,108.61 v4(83.13,108.61)
  BOTTOM w0.127: JP6.1 96.65,123.06 97.54,122.17 97.54,116.84 101.35,113.03 102.23,113.03 102.87,113.67 102.87,114.05 v3(103.5,114.68)
NETCN12_2: length 56.6
  TOP w0.127: R80.1 v1(123.19,111.12) 122.81,111.12 122.3,110.62 CN12.2 ; CN16.7 149.24,77.1 U14.1 145.94,78.11 145.8,78.25 R129.1 146.56,79.76 v1(146.69,79.76)
  BOTTOM w0.127: v1(146.69,79.76) 146.81,79.76 148.21,81.15 148.21,90.98 139.62,99.57 135.38,99.57 128.04,106.91 127.41,106.91 v1(123.19,111.12)
NETCN12_4: length 57.5
  TOP w0.127: v1(145.16,79.76) R128.2 144.4,78.34 144.64,78.11 U14.3 144.64,76.6 145.03,76.2 149.61,76.2 CN16.9 ; R87.1 123.83,109.35 v1(123.06,109.35) CN12.4
  BOTTOM w0.127: v1(145.16,79.76) 145.16,79.88 147.75,82.47 147.75,90.8 139.37,99.19 135.13,99.19 127.99,106.32 126.09,106.32 v1(123.06,109.35)
NETCN12_6: length 70.4
  TOP w0.127: R102.2 123.83,105.41 v1(123.19,105.41) ; CN12.6 v1(123.19,108.08) 123.83,108.08 R92.1 ; U14.4 144.64,74.56 R131.1 v1(146.69,73.41) 147.83,73.41 148.46,74.04 150.62,74.04 151.26,73.41 151.26,71.5 CN16.13
  L3_SIG w0.102: v1(123.19,108.08) 122.68,107.57 122.68,105.92 v1(123.19,105.41)
  BOTTOM w0.127: v1(123.19,108.08) 125.58,105.69 127.99,105.69 135.03,98.65 139.19,98.65 147.32,90.53 147.32,85.47 144.65,82.8 144.65,76.33 146.69,74.3 v1(146.69,73.41)
NETCN12_8: length 46.9
  TOP w0.127: R93.1 123.83,106.81 v1(123.19,106.81) CN12.8 ; CN16.5 147.83,83.06 145.02,83.06 144.64,83.44 U13.5 144.64,85.49 R123.1 v1(145.16,86.49)
  BOTTOM w0.127: v1(145.16,86.49) 145.16,91.44 138.81,97.79 134.24,97.79 128.14,103.89 126.11,103.89 v1(123.19,106.81)
NETCN12_10: length 62.4
  TOP w0.127: R96.1 v1(123.19,106.05) 122.68,106.05 122.17,105.54 CN12.10 ; U14.5 145.92,75.29 v1(145.92,74.3) 146.18,74.04 147.7,74.04 148.21,74.55 150.88,74.55 151.76,73.66 151.76,69.47 CN16.15
  BOTTOM w0.127: v1(145.92,74.3) 144.27,75.95 144.27,84.84 143.89,85.22 143.89,92.08 138.56,97.41 133.48,97.41 127.51,103.38 125.86,103.38 v1(123.19,106.05)
NETCN12_12: length 90.2
  TOP w0.127: SB11.1 95.12,138.58 101.45,138.58 v1(102.06,137.97) ; U13.1 v1(143.63,82.16) ; v1(123.06,104.27) CN12.12
  L3_SIG w0.102: v1(107.31,115.32) 107.31,115.14 115.39,107.06 120.27,107.06 v1(123.06,104.27)
  BOTTOM w0.127: v1(102.06,137.97) 102.06,134.42 105.03,131.44 105.03,125.09 106.17,123.95 106.17,117.47 107.31,116.33 v1(107.31,115.32) ; v1(123.06,104.27) 124.21,104.27 126.87,101.6 128.27,101.6 133.1,96.77 137.41,96.77 142.62,91.57 142.62,83.16 v1(143.63,82.16)
NETCN12_14: length 63.1
  TOP w0.127: v1(123.06,100.58) 123.19,100.58 123.71,100.06 U10.5 ; CN12.14 121.41,102.74 v1(123.57,102.74) 124.21,102.74 R102.1 ; v1(102.87,138.68) 101.22,140.34 95.25,140.34
  L3_SIG w0.102: v1(108.71,112.78) 108.76,112.78 115.37,106.17 119.63,106.17 122.78,103.02 123.29,103.02 v1(123.57,102.74)
  BOTTOM w0.127: v1(123.57,102.74) 123.57,101.09 v1(123.06,100.58) ; v1(108.71,112.78) 108.71,116.46 106.93,118.24 106.93,124.41 105.79,125.55 105.79,131.85 103,134.64 103,138.56 v1(102.87,138.68)
NETCN12_16: length 68.1
  TOP w0.127: R104.1 127.13,103.12 125.98,101.98 125.25,101.98 124.63,101.36 U10.4 123.18,101.36 v1(123.06,101.47) 122.81,101.73 CN12.16 ; SB6.1 99.64,145.21 v3(100.2,144.65)
  L3_SIG w0.102: v1(123.06,101.47) 119.63,104.9 115.7,104.9 106.83,113.77 106.83,116.18 104.32,118.69 v1(104.32,118.85)
  BOTTOM w0.127: v1(104.32,118.85) 104.32,119.08 103.89,119.51 103.89,130.68 100.46,134.11 100.46,144.4 v3(100.2,144.65)
NETCN12_18: length 77.6
  TOP w0.127: v1(89.97,150.37) 89.66,150.06 SB3.1 ; U10.3 125.22,101.36 125.09,101.23 125.09,99.69 124.84,99.44 123.49,99.44 v1(122.99,99.95) 122.73,99.95 122.22,100.46 CN12.18
  L3_SIG w0.102: v1(103.63,118.85) 103.63,118.57 105.97,116.23 105.97,113.49 115.7,103.76 119.51,103.76 122.43,100.84 122.43,100.51 v1(122.99,99.95)
  BOTTOM w0.127: v1(103.63,118.85) 103.5,118.97 103.5,130.43 99.95,133.99 99.95,142.75 99.44,143.26 99.44,146.3 96.14,149.61 94.36,149.61 93.6,150.37 v1(89.97,150.37)
NETCN12_20: length 7.7
  TOP w0.127: CN12.20 122.18,99.19 122.44,98.93 125.48,98.93 125.99,99.45 U10.1 127.87,100.06 127.89,100.08
NETCN13_2: length 4.7
  TOP w0.155: D5.D1 7.44,99.18 6.91,99.18 v1(6.77,99.04) 6.63,99.18 4.83,99.18 4.69,99.05 CN13.2
  BOTTOM w0.155: v1(6.77,99.04) 7.37,98.45 R281.1
NETCN13_3: length 4.7
  TOP w0.155: CN13.3 4.69,99.69 4.83,99.56 6.63,99.56 v1(6.77,99.7) 6.91,99.56 7.44,99.56 D5.C1
  BOTTOM w0.155: v1(6.77,99.7) 7.37,100.29 R280.1
NETCN13_4: length 7
  TOP w0.127: D5.A3 8.5,101.48 R107.1 6.35,101.6 6.35,100.97 5.73,100.34 CN13.4
NETCN14_2: length 4.7
  TOP w0.155: D6.D1 7.44,84.83 6.91,84.83 v1(6.77,84.69) 6.63,84.83 4.83,84.83 4.69,84.69 CN14.2
  BOTTOM w0.155: v1(6.77,84.69) 7.37,84.09 R284.1
NETCN14_3: length 4.7
  TOP w0.155: D6.C1 7.44,85.21 6.91,85.21 v1(6.77,85.35) 6.63,85.21 4.83,85.21 4.69,85.34 CN14.3
  BOTTOM w0.155: v1(6.77,85.35) 7.37,85.94 R283.1
NETCN14_4: length 78.8
  TOP w0.127: v1(39.37,130.56) 38.99,130.56 38.1,129.67 38.1,126.36 36.58,124.84 31.24,124.84 v1(30.99,124.59) ; D6.A3 8.5,86.75 8,87.25 v1(7.87,87.25) 6.35,87.25 5.09,85.99 CN14.4
  BOTTOM w0.127: v1(7.87,87.25) 19.94,87.25 26.04,93.34 29.21,93.34 33.91,98.04 33.91,110.57 34.89,111.54 34.89,116.88 30.99,120.78 v1(30.99,124.59) ; SB70.1 39.75,130.43 39.62,130.56 v1(39.37,130.56)
NETCN15_3: length 73.5
  TOP w0.102: U4.H12 v5(78.01,133.69)
  TOP w0.13: v1(89.17,124.24) 89.31,124.1 90.91,124.1 91.69,123.32 91.69,117.94 96.44,113.19 96.44,94.44 98.81,92.08 108.49,92.08 110.26,90.31 110.26,88.95 110.32,88.89 CN15.3
  L3_SIG w0.102: 78.36,130.56 78.38,130.57 78.99,131.19 78.99,131.7
  L3_SIG w0.104: v5(78.01,133.69) 78.22,133.48 78.61,133.48 78.99,133.1 78.99,131.7 ; 78.36,130.56 78.26,130.45 78.26,128.75 78.36,128.65 78.36,126.87 82.32,122.91 86.81,122.91 88.01,124.1 89.04,124.1 v1(89.17,124.24)
NETCN15_5: length 73.4
  TOP w0.102: U4.H13 v5(78.01,132.89)
  TOP w0.13: v1(89.17,123.58) 89.31,123.72 90.75,123.72 91.31,123.16 91.31,122.79 91.08,122.56 91.08,122.31 91.31,122.08 91.31,121.82 91.08,121.59 91.08,121.33 91.31,121.1 91.31,120.84 91.08,120.61 91.08,120.35 91.31,120.13 91.31,117.78 96.06,113.03 96.06,94.28 98.65,91.69 108.33,91.69 109.88,90.15 109.88,88.95 109.82,88.89 CN15.5
  L3_SIG w0.102: 78.61,131.7 78.61,131.67 78.61,131.67 78.61,131.35 78.2,130.94 78.11,130.84 78.11,130.84 78.09,130.83
  L3_SIG w0.104: v5(78.01,132.89) 78.22,133.1 78.45,133.1 78.61,132.94 78.61,131.7 ; v1(89.17,123.58) 89.04,123.72 88.16,123.72 86.97,122.53 82.16,122.53 77.98,126.72 77.98,128.49 77.88,128.59 77.88,130.61 78.09,130.83
NETCN15_9: length 73.4
  TOP w0.102: U4.J12 v5(77.21,133.69)
  TOP w0.13: CN15.9 108.82,88.57 108.76,88.63 108.76,89.75 107.5,91.01 98.42,91.01 93.6,95.83 93.6,108.23 93.73,108.36 94.75,108.36 95.1,108.72 95.1,109.55 94.75,109.9 93.73,109.9 93.6,110.03 93.6,111 90.04,114.55 90.04,121.59 89.66,121.97 89.26,121.97 v1(89.12,122.11)
  L3_SIG w0.104: v5(77.21,133.69) 77.21,133.69 77.57,132.98 77.57,131.31 77.04,130.78 77.04,125.46 80.52,121.97 88.98,121.97 v1(89.12,122.11)
NETCN15_11: length 73.4
  TOP w0.127: U4.J13 v5(77.21,132.89)
  TOP w0.13: CN15.11 108.32,88.54 108.38,88.6 108.38,89.59 107.34,90.63 98.27,90.63 93.22,95.68 93.22,108.39 93.57,108.74 94.59,108.74 94.72,108.87 94.72,109.39 94.59,109.52 93.57,109.52 93.22,109.87 93.22,110.84 89.66,114.4 89.66,117.86 89.43,118.08 89.43,118.34 89.66,118.57 89.66,118.83 89.43,119.06 89.43,119.32 89.66,119.55 89.66,119.81 89.43,120.04 89.43,120.29 89.66,120.52 89.66,121.43 89.5,121.59 89.26,121.59 v1(89.12,121.45)
  L3_SIG w0.104: v1(89.12,121.45) 88.98,121.59 80.37,121.59 76.66,125.3 76.66,130.15 76.48,130.33 76.48,130.53 76.66,130.71 76.66,130.94 77.19,131.47 77.19,131.9 76.99,132.1 76.99,132.31 77.19,132.51 77.19,132.86 v5(77.21,132.89)
NETCN15_15: length 73.4
  TOP w0.127: U4.F12 v5(80.41,133.69)
  TOP w0.13: CN15.15 107.32,88.51 107.26,88.57 107.26,89.13 106.45,89.94 97.95,89.94 91.49,96.4 91.49,105.77 91.14,106.13 89.66,106.13 89.53,106.25 89.53,106.77 89.66,106.9 91.14,106.9 91.49,107.25 91.49,108.09 91.14,108.44 89.66,108.44 89.53,108.57 89.53,109.09 89.66,109.22 91.14,109.22 91.49,109.57 91.49,110.29 87.38,114.41 87.38,124.08 87.05,124.41 86.67,124.41 v1(86.53,124.55)
  L3_SIG w0.104: v5(80.41,133.69) 80.75,133.03 80.8,132.94 80.8,131.62 79.22,130.05 79.22,127.89 81.94,125.17 84.43,125.17 85.09,124.51 85.1,124.51 85.2,124.41 86.39,124.41 v1(86.53,124.55)
NETCN15_17: length 73.4
  TOP w0.127: U4.F13 v5(80.41,132.89)
  TOP w0.13: CN15.17 106.82,88.56 106.88,88.62 106.88,88.98 106.29,89.56 97.79,89.56 91.11,96.24 91.11,105.61 90.98,105.74 89.51,105.74 89.15,106.1 89.15,106.93 89.51,107.28 90.98,107.28 91.11,107.41 91.11,107.93 90.98,108.06 89.51,108.06 89.15,108.41 89.15,109.25 89.51,109.6 90.98,109.6 91.11,109.73 91.11,110.13 87,114.25 87,119.94 86.82,120.11 86.82,120.37 87,120.55 87,120.81 86.82,120.99 86.82,121.25 87,121.42 87,121.68 86.82,121.86 86.82,122.12 87,122.3 87,122.56 86.82,122.74 86.82,122.99 87,123.17 87,123.92 86.89,124.03 86.67,124.03 v1(86.53,123.89)
  L3_SIG w0.104: v1(86.53,123.89) 86.39,124.03 85.03,124.03 84.27,124.79 81.78,124.79 78.84,127.73 78.84,130.21 80.42,131.78 80.42,131.98 80.21,132.18 80.21,132.38 80.49,132.66 80.49,132.8 v5(80.41,132.89)
NETCN16_3: length 39.5
  TOP w0.127: R103.1 v1(126.95,104.65) R104.2 ; CN16.3 149.99,83.44 146.19,83.44 145.94,83.69 U13.4 145.94,85.58 R124.1 v1(146.56,86.49)
  BOTTOM w0.127: v1(146.56,86.49) 146.69,86.61 146.69,90.55 139.06,98.17 134.62,98.17 128.14,104.65 v1(126.95,104.65)
NETCN16_11: length 6.4
  TOP w0.508: CN16.11 149.1,73.03 148.08,72.01 R132.1 R133.2
NETCN16_17: length 4.2
  TOP w0.127: R136.2 150.11,65.53 CN16.17
NETCN16_19: length 4.3
  TOP w0.127: CN16.19 149.86,62.48 R137.2
NETCN17_1: length 103.8
  TOP w0.127: v1(109.22,77.47) 109.35,77.34 109.35,72.64 108.86,72.16 108.86,60.72 125.14,44.45 138.18,44.45 R150.2 140.08,43.69 140.56,44.17 CN17.1
  BOTTOM w0.127: R278.1 108.58,120.9 108.08,120.4 108.08,119 110.44,116.64 110.44,110.11 109.52,109.19 109.52,90.68 110.62,89.59 110.62,81.74 109.75,80.87 109.75,78 v1(109.22,77.47)
NETCN17_2: length 103.4
  TOP w0.127: CN17.2 140.39,45.27 140.34,45.21 R149.2 138.18,45.97 124.33,45.97 109.83,60.47 109.83,77.75 v1(109.22,78.36)
  BOTTOM w0.127: R272.1 107.7,120.9 107.7,118.87 110.03,116.54 110.03,110.34 109.12,109.42 109.12,90.53 110.24,89.41 110.24,82.17 109.22,81.15 v1(109.22,78.36)
NETCN17_3: length 98.2
  TOP w0.127: v1(110.29,78.64) 110.29,78.61 110.39,78.51 110.39,60.67 123.56,47.5 138.18,47.5 R148.2 139.3,46.37 CN17.3
  BOTTOM w0.127: v1(110.29,78.64) 110.29,80.31 111,81.03 111,89.76 109.88,90.88 109.88,108.81 110.87,109.8 110.87,116.97 109.22,118.62 SB83.1
NETCN17_7: length 105
  TOP w0.127: CN17.7 138.97,50.77 R146.2 138.18,51.56 120.41,51.56 110.9,61.08 110.9,78.76 110.51,79.15 109.12,79.15 v1(108.58,78.61)
  BOTTOM w0.127: v1(108.58,78.61) 108.58,81.41 108.84,81.66 108.84,90.17 108.71,90.3 108.71,109.68 109.6,110.57 109.6,116.2 107.31,118.49 107.31,122.25 108.25,123.19 110.36,123.19 110.74,123.57 SB81.2
NETCN17_8: length 105.6
  TOP w0.127: CN17.8 139.39,51.87 R145.2 138.18,53.09 119.8,53.09 111.26,61.64 111.26,77.73 v1(112.39,78.87)
  BOTTOM w0.127: v1(112.39,78.87) 112.52,78.99 112.52,89.23 113.16,89.87 113.16,114.55 118.39,119.79 118.39,121.84 118.11,122.12 118.11,126.87 116.71,128.27 116.46,128.27 R252.1
NETCN17_10: length 5.2
  TOP w0.127: CN17.10 150.01,55.88 R142.2
NETCN18_22: length 2.8
  TOP w0.127: R153.1 80.96,37.71 CN18.22
NETCN19_1: length 10.7
  TOP w0.508: 10.64,37.31 CN19.1 ; CN19.1 10.64,41.94 ; CN19.1 9.43,39.62 ; CN19.1 11.86,39.62 ; 20.15,43.85 D13.1 ; D13.1 22.77,43.85 ; D13.1 21.46,43.34 ; D13.1 21.46,44.36
NETCN21_4: length 2.3
  TOP w0.127: R154.2 CN21.4
NETCN22_2: length 5.8
  TOP w0.155: R177.1 15.05,23.56 11.67,23.56 11.49,23.73 11.49,23.89 CN22.2
NETCN22_3: length 7.9
  TOP w0.155: CN22.3 11.11,23.89 11.11,23.58 11.51,23.18 15.05,23.18 R180.1 R182.1
NETCN23_2: length 99.9
  TOP w0.127: U24.6 137.41,22.99 v1(137.79,22.61) 137.79,20.14 138.81,19.13 139.65,19.13 D14.1 145.12,16.7 CN23.2
  BOTTOM w0.127: JP13.2 127,94.49 127,69.22 135.13,61.09 135.13,47.24 128.27,40.39 128.27,34.42 135.64,27.05 135.64,24.77 v1(137.79,22.61)
NETCN23_5: length 3.7
  TOP w0.127: R176.2 142.19,24.33 CN23.5
NETCN23_7: length 17.8
  TOP w0.127: CN23.7 143.27,17.4 D14.2 141.82,18.6 140.53,19.88 138.74,19.88 138.3,20.32 138.3,23.37 R175.1 U24.7
NETCN23_9: length 8.5
  TOP w0.127: CN23.9 148.59,24.54 147.47,25.65 R174.2
NETCN25_5: length 5.3
  TOP w0.127: R185.1 121.54,17.4 122.3,17.4 123.72,18.81 CN25.5
NETCN26_2: length 8.1
  TOP w0.127: CN26.2 116.12,1.18 117.47,2.54 R211.1
NETCN26_3: length 4.2
  TOP w0.127: R210.1 115.95,4.53 CN26.3
NETCN26_4: length 2.5
  TOP w0.127: CN26.4 107.57,5.94 R209.1
NETCN26_6: length 3.1
  TOP w0.127: R183.2 115.82,15.79 115.51,15.47 CN26.6
NETD1_1: length 106.6
  TOP w0.127: v1(95.89,157.51) 96.16,157.51 97.03,156.64 D1.1 ; U5.20 30.57,128.56 v1(29.34,129.79)
  L3_SIG w0.102: v1(95.89,157.51) 93.7,157.51 92.46,158.75 80.9,158.75 80.52,158.37 75.69,158.37 74.68,159.38 44.2,159.38 43.28,158.47 39.42,158.47 38.51,159.38 35.81,159.38 32.18,155.75 32.18,146.53 28.83,143.18 28.83,130.3 v1(29.34,129.79)
NETD1_2: length 3
  TOP w0.127: JP1.1 98.44,150.13 D1.2
NETD2_2: length 3.2
  TOP w0.127: JP4.1 33.38,135.78 D2.2
NETD5_C3: length 135.5
  TOP w0.155: D5.C3 8.56,99.56 9.09,99.56 v1(9.23,99.7)
  L3_SIG w0.13: v1(113.26,130.02) 112.99,130.29 112.99,130.46 113.14,130.61 114.22,130.61 114.81,130.02 114.81,123.25 113.28,121.72 110.31,121.72 109.07,120.47 100.15,120.47 97.82,118.14 59.21,118.14 57.51,119.84 50.47,119.84 47.88,117.25 47.88,114.5 38.05,104.67 38.05,103.17 33.27,98.4 25.78,98.4 24.18,100 10.26,100 9.82,99.56 9.37,99.56 v1(9.23,99.7)
  BOTTOM w0.127: v1(9.23,99.7) 8.89,100.04 R280.2 ; v1(113.26,130.02) 113.28,130.02 114.02,129.29 115.06,129.29 115.49,129.72 115.75,129.72 SB71.1
NETD6_C3: length 75.3
  TOP w0.155: v1(9.23,85.35) 9.09,85.21 8.56,85.21 D6.C3
  BOTTOM w0.155: SB62.1 37.47,135.18 37.29,135 36.45,135 35.94,134.49 35.94,129.92 33.99,127.97 33.99,120.54 36.22,118.31 36.22,97.18 24.25,85.21 9.37,85.21 v1(9.23,85.35) 8.89,85.69 R283.2
NETD6_D3: length 75.3
  TOP w0.155: D6.D3 8.56,84.83 9.09,84.83 v1(9.23,84.69)
  BOTTOM w0.155: SB65.1 37.47,134.47 37.31,134.62 36.61,134.62 36.32,134.34 36.32,129.76 34.37,127.81 34.37,120.7 36.6,118.47 36.6,97.02 24.41,84.83 9.37,84.83 v1(9.23,84.69) 8.89,84.35 R284.2
NETD15_2: length 1.9
  TOP w0.127: D15.2 41.29,13.97 R196.1
NETJP3_2: length 15.3
  TOP w0.127: v1(22.73,146.69) 21.97,147.45 R31.2
  BOTTOM w0.127: v1(22.73,146.69) 25.72,143.7 25.72,139.76 26.47,139.01 28.4,139.01 JP3.2
NETJP4_2: length 14.8
  TOP w0.127: v1(32.13,125.73) 32.37,125.96 U5.16
  BOTTOM w0.127: JP4.2 29.97,129.54 32.13,127.38 v1(32.13,125.73)
NETJP6_3: length 111
  TOP w0.127: v1(107.7,77.6) 107.21,77.11 107.21,53.92 102.87,49.58 102.87,34.8 96.01,27.94 JP17.3 ; v1(104.39,123.7) 103.63,124.46 JP6.3
  BOTTOM w0.127: v1(107.7,77.6) 107.31,77.98 107.31,81.92 107.85,82.45 107.85,88.52 106.81,89.56 106.81,111.89 105.16,113.54 105.16,116.97 104.78,117.35 104.78,123.32 v1(104.39,123.7)
NETJP7_2: length 20
  TOP w0.127: v1(134.09,123.7) 133.93,123.54 U6.34
  L3_SIG w0.102: v1(134.09,123.7) 136.73,126.34 138.35,126.34 140.16,128.14 142.24,128.14 146.18,124.21 JP7.2
NETJP7_3: length 46.7
  L3_SIG w0.102: JP7.3 146.43,129.16 146.43,133.45 141.33,138.56 128.47,138.56 117.25,127.33 v1(117.25,125.48)
  BOTTOM w0.127: SB77.1 v1(117.25,125.48)
NETJP8_1: length 15.4
  TOP w0.127: JP8.1 25.78,124.71 29.21,124.71 31.11,126.61 U5.17
NETJP8_2: length 125.8
  TOP w0.127: v1(35.43,120.52) 34.92,121.03 30.35,121.03 28.96,119.63 20.7,119.63 JP8.2 ; v1(71.42,31.24) 72.14,30.53 JP15.1
  BOTTOM w0.127: v1(35.43,120.52) 36.58,120.52 37.82,119.28 37.82,109.19 39.73,107.29 39.73,88.37 49.23,78.87 49.23,71.17 59.82,60.58 59.82,50.67 62.74,47.75 62.74,39.93 v1(71.42,31.24)
NETJP8_3: length 163.2
  TOP w0.127: U1.4 136.75,171.1 v1(136.53,171.32)
  BOTTOM w0.127: v1(136.53,171.32) 136.4,171.45 41.15,171.45 35.94,166.24 35.94,160.66 32.38,157.1 31.11,157.1 21.59,147.57 17.14,147.57 14.1,144.53 14.1,123.7 JP8.3
NETJP9_2: length 105.8
  TOP w0.127: v1(122.17,96.65) 116.59,96.65 111.76,101.47 JP9.2 ; v1(132.33,21.84) 132.21,21.72 U24.4
  BOTTOM w0.127: v1(132.33,21.84) 128.91,21.84 127.76,22.99 127.76,40.51 134.62,47.37 134.62,60.83 126.24,69.22 126.24,96.77 125.86,97.16 122.68,97.16 v1(122.17,96.65)
NETJP10_2: length 116.2
  TOP w0.254: U4.C1 82.93,143.41 v1(82.93,147.07) ; v1(34.29,119.25) 37.72,115.82 37.72,103.76 JP10.2
  L3_SIG w0.254: v3(68.45,153.16) 65.66,155.96 53.98,155.96 51.82,158.12 40.77,158.12 36.2,153.54 v1(35.94,153.54)
  BOTTOM w0.254: v1(82.93,147.07) 74.04,147.07 73.18,147.93 73.16,147.93 73,148.09 73,148.11 68.45,152.65 v3(68.45,153.16) ; v1(35.94,153.54) 35.94,144.27 34.29,142.62 34.29,139.05 35.12,138.23 35.12,130.23 32.84,127.96 32.84,120.95 34.29,119.51 v1(34.29,119.25)
NETJP11_2: length 11
  TOP w0.102: U9.B4 81.43,103.89 81.99,103.89 82.59,104.48 v5(82.59,104.65)
  TOP w0.127: v1(86.31,103.68) 86.31,103.23 86.79,102.74 R106.1 87.76,101.22 JP11.2
  L3_SIG w0.102: v1(86.31,103.68) 83.55,103.68 v5(82.59,104.65)
NETJP12_2: length 97.2
  TOP w0.127: U24.8 137.29,25.53 R173.1 137.41,26.42 v1(137.03,26.8) ; v1(127.51,94.36) 127.05,94.82 115.11,94.82 113.16,96.77 JP12.2
  BOTTOM w0.127: v1(137.03,26.8) 128.78,35.05 128.78,40.13 135.64,46.99 135.64,61.21 127.64,69.22 127.64,94.23 v1(127.51,94.36)
NETJP12_3: length 110.2
  TOP w0.127: v1(125.22,95.38) 115.7,95.38 JP12.3 ; v1(139.32,21.72) 139.45,21.84 R181.1
  BOTTOM w0.127: v1(139.32,21.72) 137.92,20.32 128.91,20.32 127.25,21.97 127.25,40.64 134.16,47.55 134.16,59.13 124.59,68.71 124.59,94.74 v1(125.22,95.38)
NETJP13_1: length 77.9
  TOP w0.127: R175.2 v1(139.71,24.26)
  BOTTOM w0.127: JP13.1 128.37,93.32 128.37,70.54 138.38,60.53 138.38,45.34 142.24,41.48 142.24,31.37 139.71,28.84 v1(139.71,24.26)
NETJP17_1: length 30.9
  TOP w0.127: v1(114.81,31.24) 114.97,31.08 U23.A9
  L3_SIG w0.102: JP17.1 92.84,25.27 92.84,27.05 96.9,31.11 113.33,31.11 113.74,30.71 114.27,30.71 v1(114.81,31.24)
NETJP18_1: length 22.4
  TOP w0.127: v2(117.11,29.33) 117.36,29.58 U23.C6
  L3_SIG w0.102: JP18.1 105.21,29.51 112.95,29.51 113.72,30.28 116.17,30.28 v2(117.11,29.33)
NETJP18_3: length 101.7
  TOP w0.127: v1(108.58,76.96) 107.92,76.3 107.92,53.59 103.63,49.3 103.63,33.02 JP18.3
  BOTTOM w0.127: v1(108.58,76.96) 109.42,76.96 111.43,78.97 111.43,89.92 110.19,91.16 110.19,108.58 111.25,109.65 111.25,114.55 116.08,119.38 R277.2
NETJP19_1: length 314.9
  TOP w0.127: U1.3 v1(137.7,171.32) ; v1(26.42,125.86) 26.52,125.96 U5.13
  L3_SIG w0.102: v1(30.61,96.01) 30.61,94.49 29.72,93.6 29.72,72.77 32.64,69.85 32.64,63.07 34.26,61.44 34.26,45.85 34.92,45.19 34.92,38.1 38.2,34.82 40.44,34.82 44.78,30.48 48.64,30.48 51.99,33.83 57.48,33.83 59.36,31.95 v1(59.36,31.65)
  BOTTOM w0.127: v1(30.61,96.01) 30.86,96.27 30.86,97.16 33.27,99.57 33.27,111.51 34.29,112.52 34.29,116.46 29.97,120.78 29.97,124.21 28.32,125.86 v1(26.42,125.86) 17.4,125.86 14.48,128.78 14.48,144.27 17.27,147.07 21.59,147.07 31.11,156.59 32.64,156.59 36.45,160.4 36.45,166.12 41.4,171.07 135.64,171.07 135.89,170.81 137.16,170.81 137.67,171.32 v1(137.7,171.32) ; v1(59.36,31.65) 61.04,29.97 69.47,29.97 70.74,28.7 70.74,24.26 JP19.1
NETJP19_2: length 300.7
  L3_SIG w0.102: v1(37.85,162.18) 37.97,162.31 55.5,162.31 56.39,163.19 83.06,163.19 84.07,162.18 93.47,162.18 96.27,159.38 97.54,159.38 98.93,157.99 v1(100.2,157.99) ; v1(59.31,30.86) 58.55,31.62 58.55,32.26 57.4,33.4 55.88,33.4 55.42,32.94 51.99,32.94 49.28,30.23 44.65,30.23 40.36,34.52 38.1,34.52 34.67,37.95 34.67,44.96 33.99,45.64 33.99,61.26 32.38,62.87 32.38,69.6 29.46,72.52 29.46,94.23 v1(29.97,94.74)
  BOTTOM w0.127: v1(59.31,30.86) 60.71,29.46 67.56,29.46 68.33,28.7 68.33,24.13 JP19.2 ; v1(100.2,157.99) 100.3,157.99 105.56,152.73 105.56,135.74 108.05,133.25 108.05,130.45 SB72.1 ; v1(37.85,162.18) 37.47,162.18 37.08,161.8 37.08,160.53 32.67,156.11 31.27,156.11 21.59,146.43 17.02,146.43 14.99,144.4 14.99,128.91 17.55,126.34 28.73,126.34 30.35,124.71 30.35,120.9 34.54,116.71 34.54,112.19 33.55,111.2 33.55,98.2 30.1,94.74 v1(29.97,94.74)
NETJP20_2: length 39.9
  TOP w0.127: R196.2 R195.1 38.42,15.56 38.42,17.08 37.85,17.65 JP20.2 ; U21.39 34.34,35.41 35.33,34.42 v1(35.33,33.45)
  L3_SIG w0.102: JP20.2 43.43,17.65 45.59,19.81 45.59,24.77 41.4,28.96 40.77,28.96 38.61,31.11 37.67,31.11 v1(35.33,33.45)
NETJP21_2: length 28.6
  TOP w0.127: U21.21 43.31,34.9 43.58,35.18 v1(43.94,35.18) 45.85,35.18 46.61,34.42 46.61,28.07 52.07,22.61 52.07,17.4 JP21.2
  BOTTOM w0.127: v1(43.94,35.18) 43.84,35.18 43.56,34.9 42.31,34.9 R286.2
NETL2_1: length 19.5
  TOP w0.508: R95.2 19.94,106.55 19.56,106.17 v1(17.65,106.17) ; SB13.2 v1(11.43,113.06) R78.2 L2.1
  L3_SIG w0.508: v1(17.65,106.17) 16.64,106.17 11.43,111.38 v1(11.43,113.06)
NETLD1_2: length 78.1
  TOP w0.127: LD1.2 v1(27.41,13.97) ; R194.2 v1(75.82,48.13)
  L3_SIG w0.102: v1(59.35,45.47) 59.47,45.59 68.96,45.59 70.36,46.99 74.68,46.99 v1(75.82,48.13)
  BOTTOM w0.127: v1(59.35,45.47) 59.73,45.09 59.73,39.48 57.51,37.26 57.51,32.74 56.16,31.39 56.16,28.09 54.99,26.92 51.05,26.92 46.23,22.1 46.23,16.38 42.04,12.19 29.18,12.19 v1(27.41,13.97)
NETLD2_2: length 80.7
  TOP w0.127: LD2.2 25.12,13.23 v1(25.25,13.23) ; R193.2 v1(74.3,48.13)
  L3_SIG w0.102: v1(59.31,46.23) 59.56,45.97 68.71,45.97 69.98,47.24 73.41,47.24 v1(74.3,48.13)
  BOTTOM w0.127: v1(59.31,46.23) 60.07,45.47 60.07,39.4 57.81,37.13 57.81,32.61 57.45,32.26 57.45,28.57 55.42,26.54 51.18,26.54 46.61,21.97 46.61,16 42.16,11.56 28.85,11.56 27.18,13.23 v1(25.25,13.23)
